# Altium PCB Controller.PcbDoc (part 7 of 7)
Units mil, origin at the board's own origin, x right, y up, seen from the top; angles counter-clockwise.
Board outline 9000 x 8000 mil, 6 copper layers (Top Layer, Layer 1, Layer 2, Layer 3, Layer 4, Bottom Layer), stack 61.699 mil thick; 761 components, 454 nets, 2369 pads, 1133 vias.
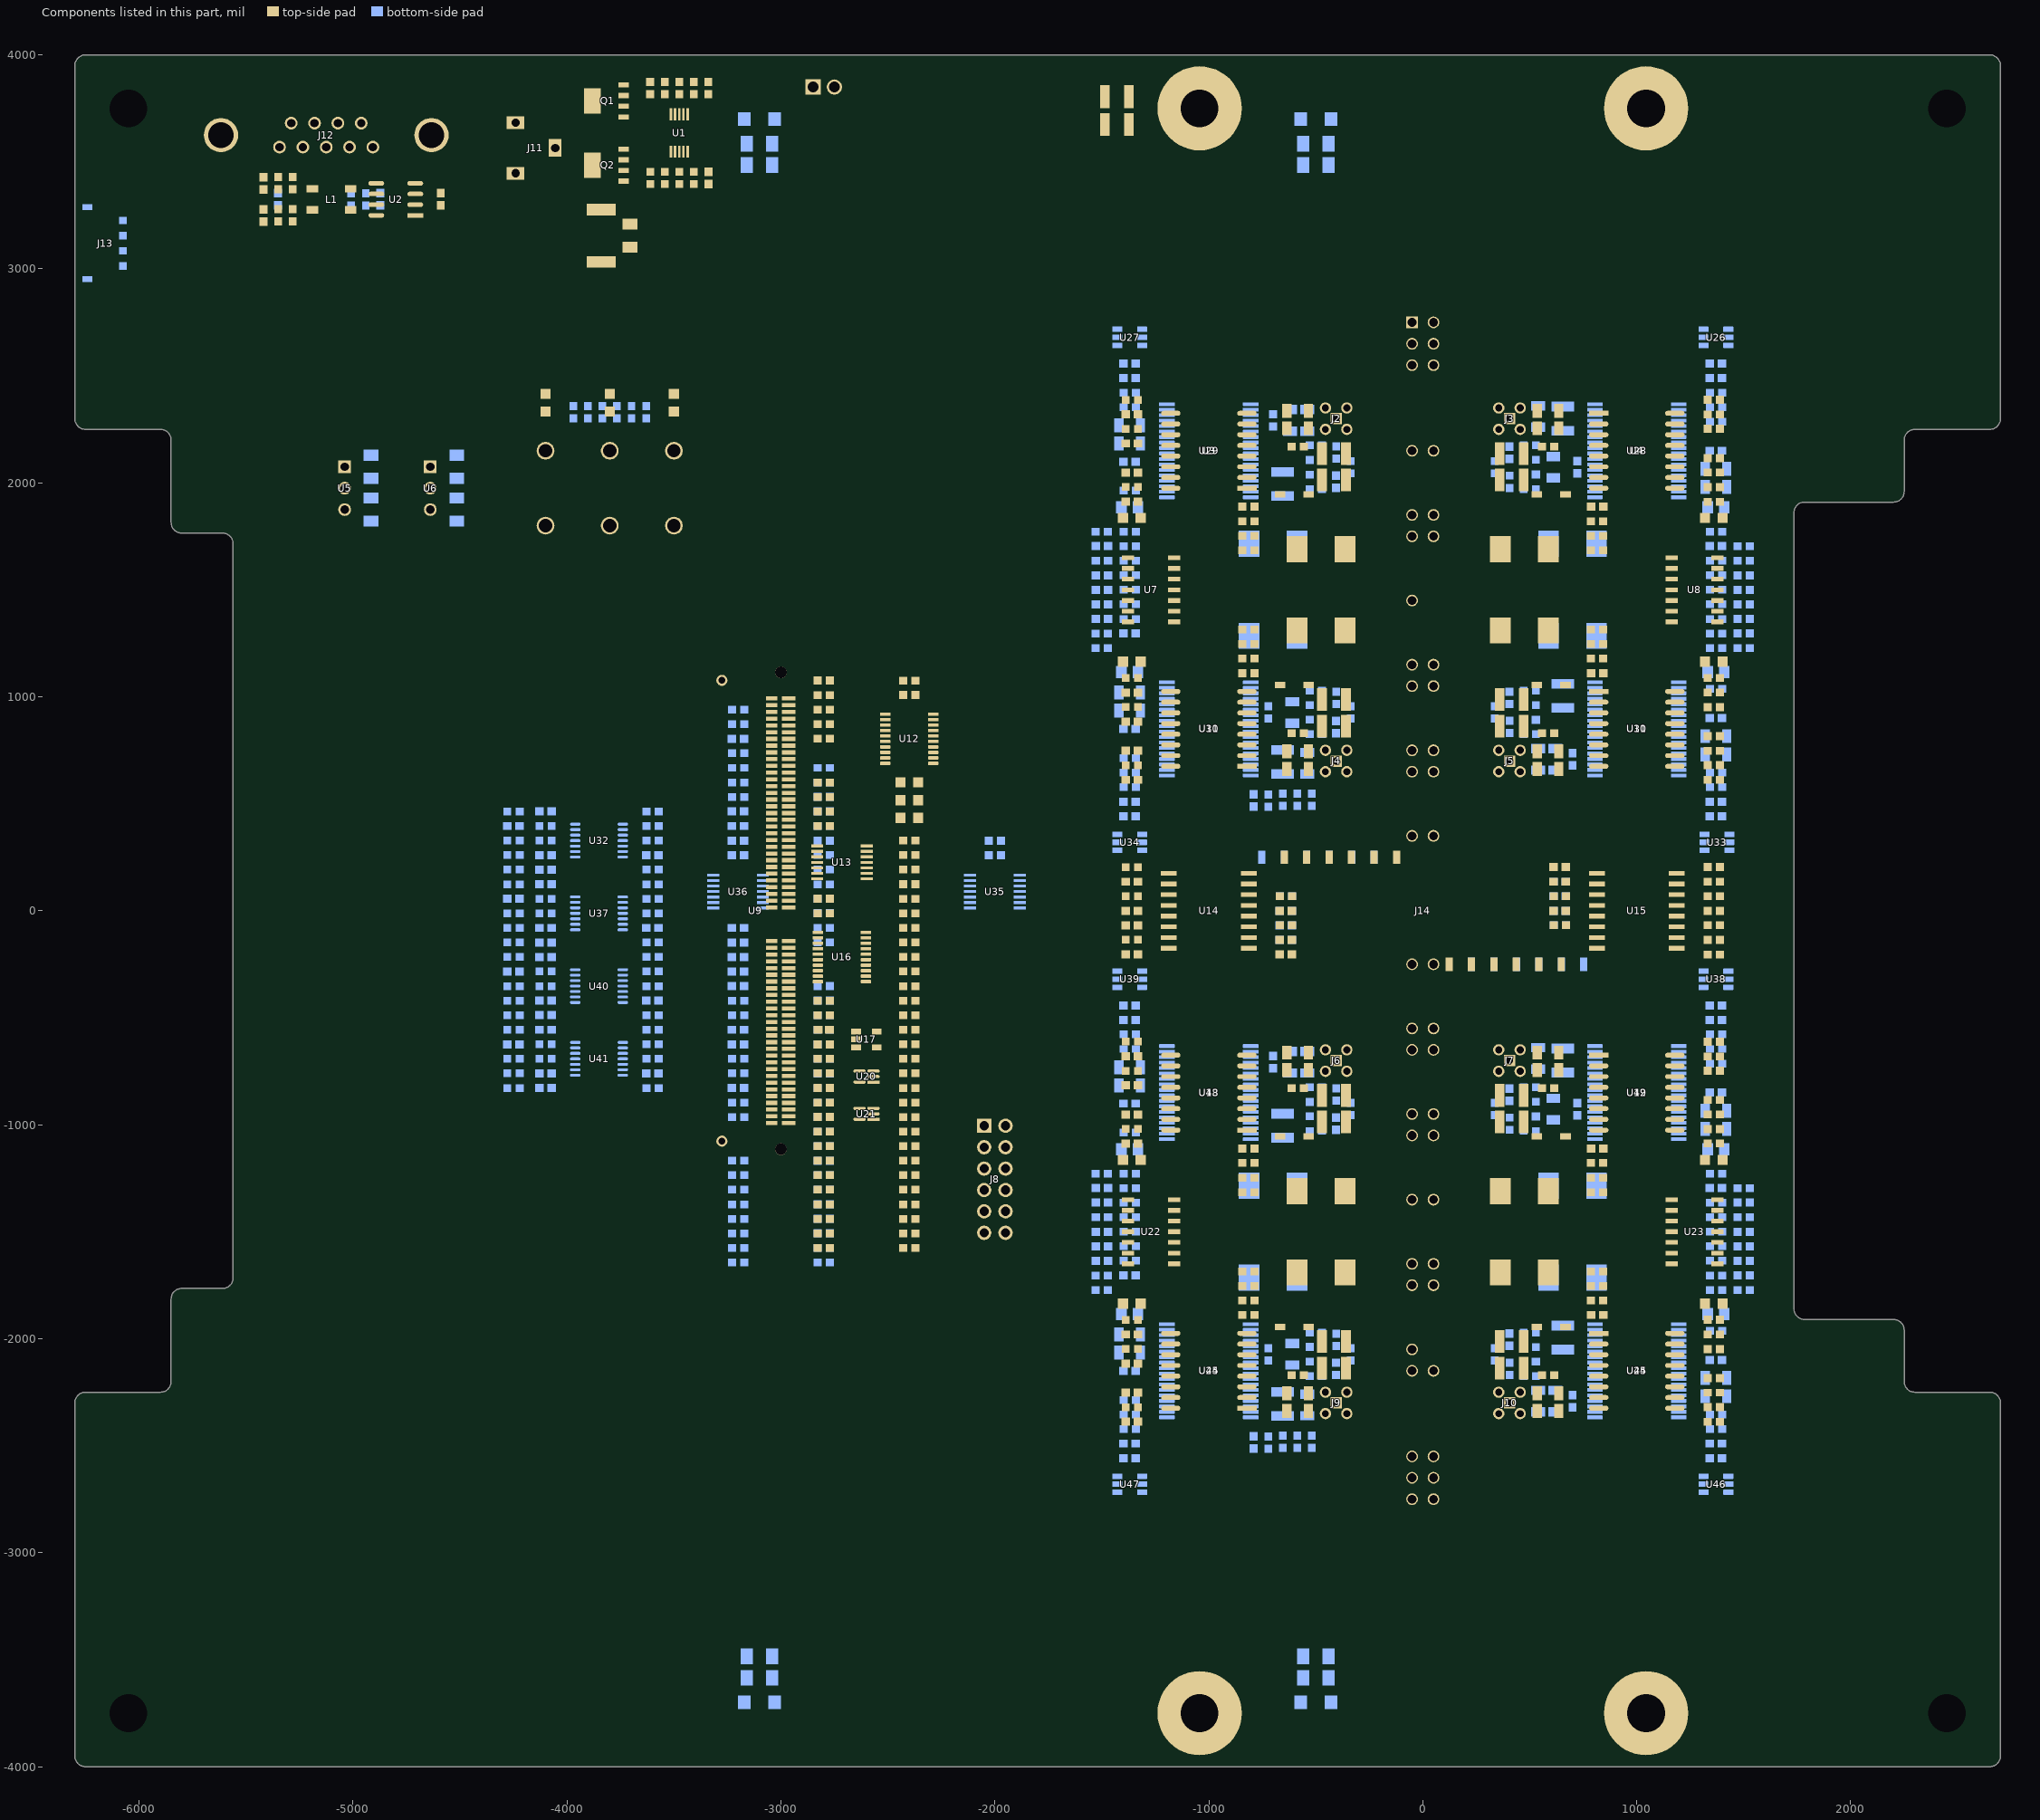
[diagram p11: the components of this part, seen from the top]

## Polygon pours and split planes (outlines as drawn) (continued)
CLMP_2P on Bottom Layer "CLMP_2P_L06_P195" (solid, pour order 195): -650,805 -650,840 -650,1030 -680,1030 -680,805
+15V_2P on Bottom Layer "+15V_2P_L06_P191" (solid, pour order 191): -845,800 -845,845 -760,845 -760,910 -705,910 -705,800
CLMP_4S on Bottom Layer "CLMP_4S_L06_P290" (solid, pour order 290): 650,-805 650,-840 650,-1030 680,-1030 680,-805
RLIM_4S on Bottom Layer "RLIM_4S_L06_P287" (solid, pour order 287): 840,-725 840,-745 765,-745 735,-775 590,-775 590,-735 600,-725
+15V_4S on Bottom Layer "+15V_4S_L06_P286" (solid, pour order 286): 845,-800 845,-845 760,-845 760,-910 705,-910 705,-800
-4V_3S on Bottom Layer "-4V_3S_L06_P262" (solid, pour order 262): -840,-1130 -840,-1160 -740,-1160 -740,-1090 -760,-1090 -760,-1030 -840,-1030
S_1S on Bottom Layer "S_1S_L06_P932" (solid, pour order 932): 755,-1915 560,-1915 560,-1980 755,-1980
-4V_1S on Bottom Layer "-4V_1S_L06_P302" (solid, pour order 302): 840,-2095 840,-2055 690,-2055 690,-2115 715,-2115 715,-2095
S_4P on Bottom Layer "NONET_L02_P-001" (solid, pour order 928): 600,2380 600,2330 740,2330 740,2380
-4V_4P on Bottom Layer "-4V_4P_L06_P032" (solid, pour order 32): 755,2415 755,2335 840,2335 840,2415
-4V_2P on Bottom Layer "-4V_2P_L06_P193" (solid, pour order 193): -715,620 -715,650 -735,670 -840,670 -840,620
GND on Bottom Layer "NONET_L-01_P-001" (solid, pour order 349): -1235,-1030 -1235,-1110 -1155,-1110 -1155,-1030
GND on Bottom Layer "NONET_L-01_P-001" (solid, pour order 357): 1235,-1970 1235,-1890 1155,-1890 1155,-1970
+12V on Bottom Layer "NONET_L-01_P-001" (solid, pour order 355): 1360,-2305 1360,-2075 1310,-2075 1310,-2045 1160,-2045 1160,-2095 1245,-2095 1245,-2140 1285,-2140 1285,-2305
GND on Bottom Layer "NONET_L-01_P-001" (solid, pour order 150): -1235,1970 -1235,1890 -1155,1890 -1155,1970
GND on Bottom Layer "NONET_L-01_P-001" (solid, pour order 238): 1235,1030 1235,1110 1155,1110 1155,1030
GND on Bottom Layer "NONET_L-01_P-001" (solid, pour order 356): 1270,-2425 1270,-2150 1235,-2150 1235,-2105 1160,-2105 1160,-2425
+15V_3P on Bottom Layer "+15V_3P_L06_P922" (solid, pour order 922): -840,2150 -840,2105 -555,2105 -555,2215 -505,2215 -505,2260 -760,2260 -760,2150
+15V_3S on Bottom Layer "+15V_3S_L06_P921" (solid, pour order 921): -840,-850 -840,-895 -555,-895 -555,-785 -505,-785 -505,-740 -760,-740 -760,-850
+15V_2P on Bottom Layer "+15V_2P_L06_P197" (solid, pour order 197): -570,955 -570,1030 -640,1030 -640,955
+15V_2S on Bottom Layer "+15V_2S_L06_P319" (solid, pour order 319): -570,-2045 -570,-1970 -640,-1970 -640,-2045
+15V_1S on Bottom Layer "+15V_1S_L06_P920" (solid, pour order 920): 840,-2150 840,-2105 555,-2105 555,-2215 505,-2215 505,-2260 760,-2260 760,-2150
+15V_4S on Bottom Layer "+15V_4S_L06_P292" (solid, pour order 292): 570,-955 570,-1030 640,-1030 640,-955
+15V_4P on Bottom Layer "+15V_4P_L06_P041" (solid, pour order 41): 570,2045 570,1970 640,1970 640,2045
GND on Bottom Layer "Bottom Layer-GND" (solid, pour order 916): 1505,-1710 ccw(c1530.12,-1709.88) 1530,-1735 1610,-1735 ccw(c1609.88,-1709.88) 1635,-1710 1635,-1355 ccw(c1609.88,-1355.12) 1610,-1330 1530,-1330 ccw(c1530.12,-1355.12) 1505,-1355
GND on Bottom Layer "Bottom Layer-GND 1" (solid, pour order 915): 1505,1290 ccw(c1530.12,1290.12) 1530,1265 1610,1265 ccw(c1609.88,1290.12) 1635,1290 1635,1645 ccw(c1609.88,1644.88) 1610,1670 1530,1670 ccw(c1530.12,1644.88) 1505,1645
CAN_MIDR on Bottom Layer "Bottom Layer-CAN_MIDR" (solid, pour order 909): 17 vertices, not listed, extent -5380,3160 -5265,3500
CAN_MIDC on Bottom Layer "Bottom Layer-CAN_MIDC" (solid, pour order 904): 17 vertices, not listed, extent -5455,3159.88 -5320,3500
GND on Bottom Layer "Bottom Layer-GND 2" (solid, pour order 883): -6014.88,3050 ccw(c-6015,3075) -5990,3074.88 -5990,3095.12 ccw(c-6015,3095) -6014.88,3120 -6135.12,3120 ccw(c-6135,3095) -6160,3095.12 -6160,3074.88 ccw(c-6135,3075) -6135.12,3050
+12V on Bottom Layer "Bottom Layer-+12V" (solid, pour order 878): -6014.88,2925 ccw(c-6015,2950) -5990,2949.88 -5990,3015.12 ccw(c-6015,3015) -6014.88,3040 -6135.12,3040 ccw(c-6135,3015) -6160,3015.12 -6160,2949.88 ccw(c-6135,2950) -6135.12,2925
+3.3V on Bottom Layer "Bottom Layer-+3.3V" (solid, pour order 873): 26 vertices, not listed, extent -5150,1785 -4870,3320
GND on Bottom Layer "Bottom Layer-GND 3" (solid, pour order 863): -4965,1915 ccw(c-4940.27,1920.29) -4940.14,1895 -4894.87,1895 ccw(c-4894.99,1919.99) -4870,1919.87 -4870,2030.12 ccw(c-4895,2030) -4894.87,2055 -4940.14,2055 ccw(c-4940.26,2029.69) -4965,2035 cw(c-4990,2035) -4989.88,2010 -5045.12,2010 ccw(c-5045,1985) -5070,1985.12 -5070,1964.88 ccw(c-5045,1965) -5045.12,1940 -4989.9,1940 cw(c-4990,1915)
GND on Bottom Layer "Bottom Layer-GND 4" (solid, pour order 862): -4565,1915 ccw(c-4540.27,1920.29) -4540.14,1895 -4494.87,1895 ccw(c-4494.99,1919.99) -4470,1919.87 -4470,2030.12 ccw(c-4495,2030) -4494.87,2055 -4540.14,2055 ccw(c-4540.26,2029.69) -4565,2035 cw(c-4590,2035) -4589.88,2010 -4645.12,2010 ccw(c-4645,1985) -4670,1985.12 -4670,1964.88 ccw(c-4645,1965) -4645.12,1940 -4589.9,1940 cw(c-4590,1915)
+12V on Bottom Layer "Bottom Layer-+12V 1" (solid, pour order 851): -4950.1,2070 -4894.88,2070 ccw(c-4892.54,2092.56) -4870,2090 -4870,2140.1 ccw(c-4895,2140) -4894.88,2165 -5045.12,2165 ccw(c-5045,2140) -5070,2140.12 -5070,2044.88 ccw(c-5045,2045) -5045.12,2020 -4999.88,2020 ccw(c-5000,2045) -4975,2045 -4975,2045.12 cw(c-4950,2045)
+5V on Bottom Layer "Bottom Layer-+5V" (solid, pour order 837): -4550.1,1880 -4494.88,1880 cw(c-4492.54,1857.44) -4470,1860 -4470,1809.9 cw(c-4495,1810) -4494.88,1785 -4645.12,1785 cw(c-4645,1810) -4670,1809.88 -4670,1905.12 cw(c-4645,1905) -4645.12,1930 -4599.88,1930 cw(c-4600,1905) -4575,1905 -4575,1904.88 ccw(c-4550,1905)
+12V on Bottom Layer "Bottom Layer-+12V 2" (solid, pour order 836): -4550.1,2070 -4494.88,2070 ccw(c-4492.54,2092.56) -4470,2090 -4470,2140.1 ccw(c-4495,2140) -4494.88,2165 -4645.12,2165 ccw(c-4645,2140) -4670,2140.12 -4670,2044.88 ccw(c-4645,2045) -4645.12,2020 -4599.88,2020 ccw(c-4600,2045) -4575,2045 -4575,2045.12 cw(c-4550,2045)
+5V on Bottom Layer "Bottom Layer-+5V 1" (solid, pour order 824): -4945,3205 -4935,3205 -4935,3245 -4905,3275 -4905,3320 -4945,3320 ccw(c-4944.03,3294.02) -4970,3295 -4970,3230 ccw(c-4944.94,3230.06)
GND on Bottom Layer "Bottom Layer-GND 5" (solid, pour order 818): -4849.88,3205 ccw(c-4850,3230) -4825,3229.88 -4825,3295.12 ccw(c-4850,3295) -4849.88,3320 -4895,3320 -4895,3270 -4925,3240 -4925,3205
NetC87_1 on Bottom Layer "Bottom Layer-NetC157_1" (solid, pour order 812): -5150,3354.88 ccw(c-5125,3355) -5125.12,3330 -4849.88,3330 ccw(c-4850,3355) -4825,3354.88 -4825,3405.12 ccw(c-4850,3405) -4849.88,3430 -5125.12,3430 ccw(c-5125,3405) -5150,3405.12
GND on Bottom Layer "NONET_L02_P-001" (solid, pour order 486): -1505,-1270 -1505,-1660 -1575,-1660 -1575,-1270
GND on Bottom Layer "NONET_L02_P-001" (solid, pour order 485): -1505,1730 -1505,1340 -1575,1340 -1575,1730
+12V on Bottom Layer "NONET_L-01_P-001" (solid, pour order 359): 1360,-1060 1360,-820 1310,-820 1310,-745 1160,-745 1160,-795 1245,-795 1245,-840 1285,-840 1285,-1060
S_4S on Bottom Layer "S_4S_L06_P294" (solid, pour order 294): 610,-620 610,-695 735,-695 735,-660 710,-660 710,-620
-4V_2S on Bottom Layer "-4V_2S_L06_P316" (solid, pour order 316): -845,-2150 -845,-1925 -840,-1920 -765,-1920 -765,-1955 -705,-1955 -705,-2060 -765,-2060 -765,-2150
-4V_2P on Bottom Layer "-4V_2P_L06_P194" (solid, pour order 194): -845,850 -845,1075 -840,1080 -765,1080 -765,1045 -705,1045 -705,940 -765,940 -765,850
-4V_4P on Bottom Layer "-4V_4P_L06_P036" (solid, pour order 36): 845,2150 845,1925 840,1920 765,1920 765,1955 705,1955 705,2060 765,2060 765,2150
GND on Bottom Layer "NONET_L-01_P-001" (solid, pour order 361): 1235,-670 1235,-590 1155,-590 1155,-670
GND on Bottom Layer "NONET_L-01_P-001" (solid, pour order 360): 1270,-1125 1270,-850 1235,-850 1235,-805 1160,-805 1160,-1125
GND on Bottom Layer "NONET_L-01_P-001" (solid, pour order 353): -1235,-2330 -1235,-2410 -1155,-2410 -1155,-2330
GND on Bottom Layer "NONET_L-01_P-001" (solid, pour order 352): -1270,-1875 -1270,-2150 -1235,-2150 -1235,-2195 -1160,-2195 -1160,-1875
+12V on Bottom Layer "NONET_L-01_P-001" (solid, pour order 351): -1360,-1945 -1360,-2180 -1310,-2180 -1310,-2255 -1160,-2255 -1160,-2205 -1245,-2205 -1245,-2160 -1285,-2160 -1285,-1945
GND on Bottom Layer "NONET_L-01_P-001" (solid, pour order 348): -1270,-575 -1270,-850 -1235,-850 -1235,-895 -1160,-895 -1160,-575
+12V on Bottom Layer "NONET_L-01_P-001" (solid, pour order 347): -1360,-695 -1360,-920 -1310,-920 -1310,-955 -1160,-955 -1160,-905 -1245,-905 -1245,-860 -1285,-860 -1285,-695
+15V_2S on Bottom Layer "Bottom Layer-+15V_2P" (solid, pour order 322): -615,-2475 -555,-2475 -555,-2395 -545,-2385 -505,-2385 -505,-2305 -595,-2305 -595,-2385 -615,-2405
S_2S on Bottom Layer "Bottom Layer-S_2P" (solid, pour order 321): -675,-2475 -635,-2475 -635,-2415 -605,-2385 -605,-2365 -605,-2305 -735,-2305 -735,-2340 -705,-2340 -705,-2385 -675,-2415
-4V_2S on Bottom Layer "-4V_2S_L06_P320" (solid, pour order 320): -510,-2280 -510,-2235 -535,-2210 -570,-2210 -570,-2280
-4V_2S on Bottom Layer "-4V_2S_L06_P318" (solid, pour order 318): -575,-2145 -575,-2055 -645,-2055 -645,-2145
CLMP_2S on Bottom Layer "CLMP_2S_L06_P317" (solid, pour order 317): -650,-2195 -650,-2160 -650,-1970 -680,-1970 -680,-2195
-4V_2S on Bottom Layer "-4V_2S_L06_P315" (solid, pour order 315): -715,-2380 -715,-2350 -735,-2330 -840,-2330 -840,-2380
RLIM_2S on Bottom Layer "RLIM_2S_L06_P314" (solid, pour order 314): -840,-2275 -840,-2255 -765,-2255 -735,-2225 -590,-2225 -590,-2265 -600,-2275
+15V_2S on Bottom Layer "+15V_2S_L06_P313" (solid, pour order 313): -845,-2200 -845,-2155 -760,-2155 -760,-2090 -705,-2090 -705,-2200
S_1S on Bottom Layer "S_1S_L06_P300" (solid, pour order 300): 575,-2380 575,-2305 440,-2305 440,-2380
-4V_1S on Bottom Layer "-4V_1S_L06_P299" (solid, pour order 299): 840,-2380 840,-2155 765,-2155 765,-2265 585,-2265 585,-2380
RLIM_1S on Bottom Layer "RLIM_1S_L06_P296" (solid, pour order 296): 840,-2045 840,-2000 575,-2000 575,-2080 685,-2080 685,-2045
-4V_4S on Bottom Layer "-4V_4S_L06_P295" (solid, pour order 295): 510,-720 510,-765 535,-790 570,-790 570,-720
+15V_4S on Bottom Layer "+15V_4S_L06_P293" (solid, pour order 293): 505,-620 505,-695 600,-695 600,-620
-4V_4S on Bottom Layer "-4V_4S_L06_P291" (solid, pour order 291): 575,-855 575,-945 645,-945 645,-855
-4V_4S on Bottom Layer "-4V_4S_L06_P289" (solid, pour order 289): 845,-850 845,-1075 840,-1080 765,-1080 765,-1045 705,-1045 705,-940 765,-940 765,-850
-4V_4S on Bottom Layer "-4V_4S_L06_P288" (solid, pour order 288): 715,-620 715,-650 735,-670 840,-670 840,-620
-4V_3S on Bottom Layer "-4V_3S_L06_P267" (solid, pour order 267): -840,-905 -840,-945 -690,-945 -690,-885 -715,-885 -715,-905
S_3S on Bottom Layer "S_3S_L06_P265" (solid, pour order 265): -575,-620 -575,-695 -440,-695 -440,-620
-4V_3S on Bottom Layer "-4V_3S_L06_P264" (solid, pour order 264): -840,-620 -840,-845 -765,-845 -765,-735 -585,-735 -585,-620
S_3S on Bottom Layer "S_3S_L06_P263" (solid, pour order 263): -755,-1085 -560,-1085 -560,-1020 -755,-1020
RLIM_3S on Bottom Layer "RLIM_3S_L06_P261" (solid, pour order 261): -840,-955 -840,-1000 -575,-1000 -575,-920 -685,-920 -685,-955
HLDOO_P on Bottom Layer "NONET_L02_P-001" (solid, pour order 250): -760,30 -760,-90 -645,-90 -645,30
GND on Bottom Layer "NONET_L-01_P-001" (solid, pour order 149): -1270,2425 -1270,2150 -1235,2150 -1235,2105 -1160,2105 -1160,2425
GND on Bottom Layer "NONET_L-01_P-001" (solid, pour order 241): -1270,1125 -1270,850 -1235,850 -1235,805 -1160,805 -1160,1125
GND on Bottom Layer "NONET_L-01_P-001" (solid, pour order 242): -1235,670 -1235,590 -1155,590 -1155,670
GND on Bottom Layer "NONET_L-01_P-001" (solid, pour order 245): 1270,1875 1270,2150 1235,2150 1235,2195 1160,2195 1160,1875
GND on Bottom Layer "NONET_L-01_P-001" (solid, pour order 246): 1235,2330 1235,2410 1155,2410 1155,2330
+12V on Bottom Layer "NONET_L-01_P-001" (solid, pour order 244): 1360,1945 1360,2180 1310,2180 1310,2255 1160,2255 1160,2205 1245,2205 1245,2160 1285,2160 1285,1945
+12V on Bottom Layer "NONET_L-01_P-001" (solid, pour order 240): -1360,1054.3 -1360,820 -1310,820 -1310,745 -1160,745 -1160,795 -1245,795 -1245,840 -1285,840 -1285,1054.3
+12V on Bottom Layer "NONET_L-01_P-001" (solid, pour order 236): 1360,695 1360,920 1310,920 1310,955 1160,955 1160,905 1245,905 1245,860 1285,860 1285,695
+12V on Bottom Layer "NONET_L-01_P-001" (solid, pour order 148): -1360,2305 -1360,2080 -1310,2080 -1310,2045 -1160,2045 -1160,2095 -1245,2095 -1245,2140 -1285,2140 -1285,2305
+15V_2P on Bottom Layer "Bottom Layer-+15V_2P" (solid, pour order 206): -615,525 -555,525 -555,605 -545,615 -505,615 -505,695 -595,695 -595,615 -615,595
-4V_2P on Bottom Layer "-4V_2P_L06_P200" (solid, pour order 200): -510,720 -510,765 -535,790 -570,790 -570,720
-4V_2P on Bottom Layer "-4V_2P_L06_P196" (solid, pour order 196): -575,855 -575,945 -645,945 -645,855
-4V_1P on Bottom Layer "-4V_1P_L06_P112" (solid, pour order 112): 840,905 840,945 690,945 690,885 715,885 715,905
+15V_1P on Bottom Layer "+15V_1P_L06_P111" (solid, pour order 111): 840,850 840,895 555,895 555,785 505,785 505,740 760,740 760,850
S_1P on Bottom Layer "S_1P_L06_P110" (solid, pour order 110): 575,620 575,695 440,695 440,620
-4V_1P on Bottom Layer "-4V_1P_L06_P109" (solid, pour order 109): 840,620 840,845 765,845 765,735 585,735 585,620
S_1P on Bottom Layer "S_1P_L06_P108" (solid, pour order 108): 755,1085 560,1085 560,1020 755,1020
RLIM_1P on Bottom Layer "RLIM_1P_L06_P106" (solid, pour order 106): 840,955 840,1000 575,1000 575,920 685,920 685,955
-4V_3P on Bottom Layer "-4V_3P_L06_P016" (solid, pour order 16): -840,2380 -840,2155 -765,2155 -765,2265 -585,2265 -585,2380
-4V_4P on Bottom Layer "-4V_4P_L06_P046" (solid, pour order 46): 510,2280 510,2235 535,2210 570,2210 570,2280
S_4P on Bottom Layer "S_4P_L06_P044" (solid, pour order 44): 610,2380 610,2305 735,2305 735,2340 710,2340 710,2380
+15V_4P on Bottom Layer "+15V_4P_L06_P043" (solid, pour order 43): 505,2380 505,2305 600,2305 600,2380
-4V_4P on Bottom Layer "-4V_4P_L06_P040" (solid, pour order 40): 575,2145 575,2055 645,2055 645,2145
S_3P on Bottom Layer "S_3P_L06_P004" (solid, pour order 4): -755,1915 -560,1915 -560,1980 -755,1980
RLIM_3P on Bottom Layer "RLIM_3P_L06_P001" (solid, pour order 1): -840,2045 -840,2000 -575,2000 -575,2080 -685,2080 -685,2045
-4V_3P on Bottom Layer "-4V_3P_L06_P023" (solid, pour order 23): -840,2095 -840,2055 -690,2055 -690,2115 -715,2115 -715,2095
S_3P on Bottom Layer "S_3P_L06_P017" (solid, pour order 17): -575,2380 -575,2305 -440,2305 -440,2380
+5V on Layer 3 "Layer 3-+5V 1" (solid, pour order 711): 27 vertices, not listed, extent -100,-3900 1635,3900
+5V on Layer 3 "Layer 3-+5V" (solid, pour order 705): 59 vertices, not listed, extent -6200,-3900 115,3900
-4V_3P on Layer 3 "Layer 1-S_4P" (solid, pour order 114): -350,1910 ccw(c-350,1935) -325,1935 -325,2355.33 ccw(c-350,2355) -349.88,2380 -845.12,2380 ccw(c-845,2355) -870,2355.12 -870,1644.88 ccw(c-845,1645) -845.12,1620 -784.88,1620 ccw(c-785,1645) -760,1644.88 -760,1830 -680.02,1909.98
-4V_1S on Layer 3 "Layer 3--4V_1P" (solid, pour order 334): 349.88,-2380 845.12,-2380 ccw(c845,-2355) 870,-2355.12 870,-1644.88 ccw(c845.01,-1645) 845.12,-1620 784.88,-1620 ccw(c784.99,-1644.99) 760,-1644.88 760,-1830 680.02,-1909.98 349.92,-1910 ccw(c350,-1935) 325,-1935 325,-2355 ccw(c350,-2355)
-4V_4P on Layer 3 "Layer 3--4V_3P" (solid, pour order 179): 784.88,1615 840.12,1615 ccw(c840,1640) 865,1639.88 865,2385.12 ccw(c840,2385) 840.12,2410 334.88,2410 ccw(c334.93,2385.06) 310,2385.12 310,1955 ccw(c335,1955) 334.88,1930 685,1930 760,1855 760,1639.88 ccw(c785,1640)
-4V_1P on Layer 3 "Layer 3--4V_1P" (solid, pour order 145): 349.88,620 845.12,620 ccw(c845,645) 870,644.88 870,1355.12 ccw(c845.01,1355) 845.12,1380 784.88,1380 ccw(c784.99,1355.01) 760,1355.12 760,1170 680.02,1090.02 349.92,1090 ccw(c350,1065) 325,1065 325,645 ccw(c350,645)
-4V_2P on Layer 3 "Layer 3--4V_2P" (solid, pour order 229): 17 vertices, not listed, extent -865,455 -290,1385
-4V_4S on Layer 3 "Layer 3--4V_3P" (solid, pour order 335): 784.88,-1385 840.12,-1385 ccw(c840,-1360) 865,-1360.12 865,-629.88 ccw(c840,-630) 840.12,-605 334.88,-605 ccw(c334.93,-629.93) 310,-629.88 310,-1045 ccw(c335,-1045) 334.88,-1070 685,-1070 760,-1145 760,-1360.12 ccw(c785,-1360)
-4V_3S on Layer 3 "Layer 1-S_4P" (solid, pour order 328): -350,-1090 ccw(c-350,-1065) -325,-1065 -325,-644.67 ccw(c-350,-645) -349.88,-620 -845.12,-620 ccw(c-845,-645) -870,-644.88 -870,-1355.12 ccw(c-845,-1355) -845.12,-1380 -784.88,-1380 ccw(c-785,-1355) -760,-1355.12 -760,-1170 -680.02,-1090.02
-4V_2S on Layer 3 "Layer 3--4V_2P" (solid, pour order 336): 17 vertices, not listed, extent -865,-2545 -290,-1615
VIN on Layer 3 "Layer 3-VIN" (solid, pour order 517): -3349.88,2940 ccw(c-3350,2965) -3325,2964.88 -3325,3875.12 ccw(c-3350,3875) -3349.88,3900 -4295.12,3900 ccw(c-4295,3875) -4320,3875.12 -4320,2964.88 ccw(c-4295,2965) -4295.12,2940
GND on Layer 1 "Layer 1-GND 1" (solid, pour order 664): 27 vertices, not listed, extent -100,-3900 1635,3900
GND on Layer 1 "Layer 1-GND" (solid, pour order 670): 51 vertices, not listed, extent -6200,-3900 115,3900
S_3P on Layer 1 "Layer 1-S_3P" (solid, pour order 411): 17 vertices, not listed, extent -870,1620 80,2380
S_4P on Layer 1 "Layer 1-S_4P 1" (solid, pour order 409): 18 vertices, not listed, extent -75,1615 865,2410
S_1P on Layer 1 "Layer 1-S_1P" (solid, pour order 137): 23 vertices, not listed, extent -85,620 870,1380
S_2P on Layer 1 "Layer 1-S_2P" (solid, pour order 222): 21 vertices, not listed, extent -865,455 95,1385
S_4S on Layer 1 "Layer 1-S_4S" (solid, pour order 431): 19 vertices, not listed, extent -90,-1385 865,-505
S_2S on Layer 1 "Layer 1-S_2S" (solid, pour order 449): 29 vertices, not listed, extent -865,-2545 80,-1615
S_1S on Layer 1 "Layer 1-S_1S" (solid, pour order 453): 20 vertices, not listed, extent -85,-2380 870,-1595
S_3S on Layer 1 "Layer 1-S_3S" (solid, pour order 401): 18 vertices, not listed, extent -870,-1380 75,-620
GND_P on Layer 1 "Layer 1-GND_P" (solid, pour order 422): -559.88,-235 ccw(c-560,-210) -535,-210.12 -535,85.12 ccw(c-560,85) -559.88,110 -710.12,110 cw(c-710,135) -735,134.88 -735,420.12 ccw(c-760,420) -759.88,445 -840.12,445 ccw(c-840,420) -865,420.12 -865,-210.12 ccw(c-840,-210) -840.12,-235
GND_S on Layer 1 "Layer 1-GND_S" (solid, pour order 434): 559.88,-110 710.12,-110 cw(c710,-135) 735,-134.88 735,-570.12 ccw(c760,-570) 759.88,-595 840.12,-595 ccw(c840,-570) 865,-570.12 865,210.12 ccw(c840,210) 840.12,235 559.88,235 ccw(c560,210) 535,210.12 535,-85.12 ccw(c560,-85)
+12V on Layer 2 "Layer 2-+12V 1" (solid, pour order 796): 27 vertices, not listed, extent -100,-3900 1635,3900
+12V on Layer 2 "Layer 2-+12V" (solid, pour order 799): 59 vertices, not listed, extent -6200,-3900 115,3900
+3.3V on Layer 2 "Layer 2-+3.3V" (solid, pour order 734): -2054.88,-1990 ccw(c-2055,-1965) -2030,-1965.12 -2030,2225.12 ccw(c-2055,2225) -2054.88,2250 -3565.12,2250 ccw(c-3565,2225) -3590,2225.12 -3590,1949.88 cw(c-3615,1950) -3614.88,1925 -5435.12,1925 ccw(c-5435,1900) -5460,1900.12 -5460,-1965.12 ccw(c-5432.44,-1962.41) -5430,-1990
+15V_3P on Layer 2 "Layer 1-S_4P" (solid, pour order 113): -350,1910 ccw(c-350,1935) -325,1935 -325,2355.33 ccw(c-350,2355) -349.88,2380 -845.12,2380 ccw(c-845,2355) -870,2355.12 -870,1644.88 ccw(c-845,1645) -845.12,1620 -784.88,1620 ccw(c-785,1645) -760,1644.88 -760,1830 -680.02,1909.98
+15V_1S on Layer 2 "Layer 2-+15V_1P" (solid, pour order 371): 349.88,-2380 845.12,-2380 ccw(c845,-2355) 870,-2355.12 870,-1644.88 ccw(c845.01,-1645) 845.12,-1620 784.88,-1620 ccw(c784.99,-1644.99) 760,-1644.88 760,-1830 680.02,-1909.98 349.92,-1910 ccw(c350,-1935) 325,-1935 325,-2355 ccw(c350,-2355)
+15V_4P on Layer 2 "Layer 2-+15V_3P" (solid, pour order 178): 784.88,1615 840.12,1615 ccw(c840,1640) 865,1639.88 865,2385.12 ccw(c840,2385) 840.12,2410 334.88,2410 ccw(c334.93,2385.06) 310,2385.12 310,1955 ccw(c335,1955) 334.88,1930 685,1930 760,1855 760,1639.88 ccw(c785,1640)
+15V_1P on Layer 2 "Layer 2-+15V_1P" (solid, pour order 144): 349.88,620 845.12,620 ccw(c845,645) 870,644.88 870,1355.12 ccw(c845.01,1355) 845.12,1380 784.88,1380 ccw(c784.99,1355.01) 760,1355.12 760,1170 680.02,1090.02 349.92,1090 ccw(c350,1065) 325,1065 325,645 ccw(c350,645)
+15V_2P on Layer 2 "Layer 2-+15V_2P" (solid, pour order 228): 17 vertices, not listed, extent -865,455 -290,1385
+15V_4S on Layer 2 "Layer 2-+15V_3P" (solid, pour order 374): 784.88,-1385 840.12,-1385 ccw(c840,-1360) 865,-1360.12 865,-629.88 ccw(c840,-630) 840.12,-605 334.88,-605 ccw(c334.93,-629.93) 310,-629.88 310,-1045 ccw(c335,-1045) 334.88,-1070 685,-1070 760,-1145 760,-1360.12 ccw(c785,-1360)
+15V_3S on Layer 2 "Layer 1-S_4P" (solid, pour order 327): -350,-1090 ccw(c-350,-1065) -325,-1065 -325,-644.67 ccw(c-350,-645) -349.88,-620 -845.12,-620 ccw(c-845,-645) -870,-644.88 -870,-1355.12 ccw(c-845,-1355) -845.12,-1380 -784.88,-1380 ccw(c-785,-1355) -760,-1355.12 -760,-1170 -680.02,-1090.02
+15V_2S on Layer 2 "Layer 2-+15V_2P" (solid, pour order 333): 17 vertices, not listed, extent -865,-2545 -290,-1615
GND on Layer 4 "Layer 1-GND 1" (solid, pour order 923): 27 vertices, not listed, extent -100,-3900 1635,3900
GND on Layer 4 "Layer 1-GND" (solid, pour order 924): 51 vertices, not listed, extent -6200,-3900 115,3900
S_3P on Layer 4 "Layer 1-S_4P" (solid, pour order 115): -350,1910 ccw(c-350,1935) -325,1935 -325,2355.33 ccw(c-350,2355) -349.88,2380 -845.12,2380 ccw(c-845,2355) -870,2355.12 -870,1644.88 ccw(c-845,1645) -845.12,1620 -784.88,1620 ccw(c-785,1645) -760,1644.88 -760,1830 -680.02,1909.98
S_4P on Layer 4 "Layer 4-S_3P" (solid, pour order 180): 784.88,1615 840.12,1615 ccw(c840,1640) 865,1639.88 865,2385.12 ccw(c840,2385) 840.12,2410 334.88,2410 ccw(c334.93,2385.06) 310,2385.12 310,1955 ccw(c335,1955) 334.88,1930 685,1930 760,1855 760,1639.88 ccw(c785,1640)
S_1P on Layer 4 "Layer 4-S_1P" (solid, pour order 146): 349.88,620 845.12,620 ccw(c845,645) 870,644.88 870,1355.12 ccw(c845.01,1355) 845.12,1380 784.88,1380 ccw(c784.99,1355.01) 760,1355.12 760,1170 680.02,1090.02 349.92,1090 ccw(c350,1065) 325,1065 325,645 ccw(c350,645)
S_2P on Layer 4 "Layer 4-S_2P" (solid, pour order 230): 17 vertices, not listed, extent -865,455 -290,1385
S_4S on Layer 4 "Layer 4-S_3P" (solid, pour order 338): 784.88,-1385 840.12,-1385 ccw(c840,-1360) 865,-1360.12 865,-629.88 ccw(c840,-630) 840.12,-605 334.88,-605 ccw(c334.93,-629.93) 310,-629.88 310,-1045 ccw(c335,-1045) 334.88,-1070 685,-1070 760,-1145 760,-1360.12 ccw(c785,-1360)
GND_P on Layer 4 "Layer 1-GND_P" (solid, pour order 800): -559.88,-235 ccw(c-560,-210) -535,-210.12 -535,85.12 ccw(c-560,85) -559.88,110 -710.12,110 cw(c-710,135) -735,134.88 -735,420.12 ccw(c-760,420) -759.88,445 -840.12,445 ccw(c-840,420) -865,420.12 -865,-210.12 ccw(c-840,-210) -840.12,-235
GND_S on Layer 4 "Layer 1-GND_S" (solid, pour order 801): 559.88,-110 710.12,-110 cw(c710,-135) 735,-134.88 735,-570.12 ccw(c760,-570) 759.88,-595 840.12,-595 ccw(c840,-570) 865,-570.12 865,210.12 ccw(c840,210) 840.12,235 559.88,235 ccw(c560,210) 535,210.12 535,-85.12 ccw(c560,-85)
S_2S on Layer 4 "Layer 4-S_2P" (solid, pour order 339): 17 vertices, not listed, extent -865,-2545 -290,-1615
S_1S on Layer 4 "Layer 4-S_1P" (solid, pour order 337): 349.88,-2380 845.12,-2380 ccw(c845,-2355) 870,-2355.12 870,-1644.88 ccw(c845.01,-1645) 845.12,-1620 784.88,-1620 ccw(c784.99,-1644.99) 760,-1644.88 760,-1830 680.02,-1909.98 349.92,-1910 ccw(c350,-1935) 325,-1935 325,-2355 ccw(c350,-2355)
S_3S on Layer 4 "Layer 1-S_4P" (solid, pour order 329): -350,-1090 ccw(c-350,-1065) -325,-1065 -325,-644.67 ccw(c-350,-645) -349.88,-620 -845.12,-620 ccw(c-845,-645) -870,-644.88 -870,-1355.12 ccw(c-845,-1355) -845.12,-1380 -784.88,-1380 ccw(c-785,-1355) -760,-1355.12 -760,-1170 -680.02,-1090.02

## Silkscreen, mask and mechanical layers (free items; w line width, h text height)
Top Overlay:
  drawing of 281 lines, arcs and shapes, not listed
  text "+" at -4440,3780 h60
  text "+" at -2861.66,3672.51 h35
  text "-" at -2761.66,3672.51 h35
  text "-" at -4440,3510.01 h60
  text "(G3P)" at -477.89,2391 h35
  text "(G4P)" at 332.11,2391 h35
  text "(ROFF)" at -319,2091.51 h35
  text "(RON)" at 173.21,2091.51 h35
  text "(+12V)" at -4187.47,2032.51 h35
  text "(+5V)" at -3872.89,2032.51 h35
  text "(+3.3V)" at -3604.97,2032.51 h35
  text "(RON)" at -319,1967.51 h35
  text "(ROFF)" at 138.23,1967.51 h35
  text "(FLT3P)" at -1284,1818.51 h35
  text "(FLT4P)" at 1068.24,1818.51 h35
  text "(GND)" at -4172.89,1682.51 h35
  text "(GND)" at -3872.89,1682.51 h35
  text "(GND)" at -3572.89,1682.51 h35
  text "(FLT2P)" at -1284,1146.51 h35
  text "(FLT1P)" at 1074.07,1146.51 h35
  text "(ROFF)" at -319,941.51 h35
  text "(RON)" at 173.21,941.51 h35
  text "(RON)" at -319,817.51 h35
  text "(ROFF)" at 138.23,817.51 h35
  text "(G2P)" at -477.89,574.01 h35
  text "(G1P)" at 335.02,574.01 h35
  text "3.3" at -2118.74,-367.49 h35
  text "5V" at -1954.16,-367.49 h35
  text "(POWER)" at -1829,-367.49 h35
  text "B4" at -2104.16,-467.49 h35
  text "B3" at -1954.16,-467.49 h35
  text "(ADC)" at -1829,-467.49 h35
  text "8A" at -2104.16,-567.49 h35
  text "8B" at -1954.16,-567.49 h35
  text "(EPWM)" at -1829,-567.49 h35
  text "(G3S)" at -477.89,-609 h35
  text "(G4S)" at 332.11,-609 h35
  text "8" at -2086.66,-667.49 h35
  text "9" at -1936.66,-667.49 h35
  text "(GPIO)" at -1829,-717.49 h35
  text "22" at -2104.16,-767.49 h35
  text "23" at -1954.16,-767.49 h35
  text "GND" at -2121.65,-867.49 h35
  text "12V" at -1968.74,-867.49 h35
  text "(POWER)" at -1829,-867.49 h35
  text "(ROFF)" at -319,-908.49 h35
  text "(RON)" at 173.21,-908.49 h35
  text "(RON)" at -319,-1032.49 h35
  text "(ROFF)" at 138.23,-1032.49 h35
  text "(FLT3S)" at -1284,-1181.49 h35
  text "(FLT4S)" at 1068.24,-1181.49 h35
  text "(FLT2S)" at -1284,-1853.49 h35
  text "(FLT1S)" at 1074.07,-1853.49 h35
  text "(ROFF)" at -319,-2058.49 h35
  text "(RON)" at 173.21,-2058.49 h35
  text "(RON)" at -319,-2182.49 h35
  text "(ROFF)" at 138.23,-2182.49 h35
  text "(G2S)" at -477.89,-2425.99 h35
  text "(G1S)" at 335.02,-2425.99 h35
  text "WOLFPACK 60KW DAB - CONTROL" at -799.74,-3790 h60
  text "CRD60DD12N-GMB V2.0, 02/2025" at -819.73,-3885.01 h60
Bottom Overlay:
  lines w8: -4739.7,-181.7 -4297.48,-181.7 ; -4737.7,157.7 -4297.48,157.7 ; -4737.3,-522.3 -4297.48,-522.3
  lines w10: -4740,-860 -4738.3,-861.7 ; -4740,-182 -4739.7,-181.7 ; -4740,160 -4737.7,157.7 ; -4737.7,497.7 -4740,500 ; -500,-2395 -495,-2400 -460,-2400 ; -500,605 -495,600 -460,600 ; -485,-1935 -485,-1920 ; -485,-1065 -485,-1080 ; -485,1065 -485,1080 ; -485,1935 -485,1920 ; -300,-2073 -285,-2073 ; -300,-927 -285,-927 ; -300,927 -285,927 ; -300,2073 -285,2073 ; 285,-2073 300,-2073 ; 285,-926.09 300,-926.09 ; 285,927 300,927 ; 285,2073 300,2073 ; 485,-1935 485,-1920 ; 485,1065 485,1080 ; 485,1935 485,1920 ; 485.91,-1080 485.91,-1065 ; -4740,500 -4360,500 -4360,-865 -4740,-865 -4740,500 ; -485,-1920 -315,-1920 -315,-1675 -485,-1675 -485,-1920 ; -485,-1080 -315,-1080 -315,-1325 -485,-1325 -485,-1080 ; -485,1080 -315,1080 -315,1325 -485,1325 -485,1080 ; -485,1920 -315,1920 -315,1675 -485,1675 -485,1920 ; 485,-1920 315,-1920 315,-1675 485,-1675 485,-1920 ; 485,1080 315,1080 315,1325 485,1325 485,1080 ; 485,1920 315,1920 315,1675 485,1675 485,1920 ; -460,-2565 -325,-2565 -325,-2399 -460,-2399 -460,-2565 ; -460,435 -325,435 -325,601 -460,601 -460,435 ; -285,-2238 -150,-2238 -150,-1908 -285,-1908 -285,-2238 ; -285,-1092 -150,-1092 -150,-762 -285,-762 -285,-1092 ; -285,762 -150,762 -150,1092 -285,1092 -285,762 ; -285,1908 -150,1908 -150,2238 -285,2238 -285,1908 ; 150,-2238 285,-2238 285,-1908 150,-1908 150,-2238 ; 150,-1091.09 285,-1091.09 285,-761.09 150,-761.09 150,-1091.09 ; 150,762 285,762 285,1092 150,1092 150,762 ; 150,1908 285,1908 285,2238 150,2238 150,1908 ; 315,-1325 485,-1325 485,-1080 315,-1080 315,-1325
  text "L" at -6007.51,3236.66 h35 r90
  text "H" at -6007.51,3167.1 h35 r90
  text "-" at -6007.51,3096.23 h35 r90
  text "+" at -6007.51,3025.36 h35 r90
Board Shape:
  the board outline again, w10
Drill Drawing:
  drawing of 201 lines, arcs and shapes, not listed
  text "Symbol" at -6202.5,6628.94 h72
  text "Count" at -5696.62,6628.94 h72
  text "Hole Size" at -5046.8,6628.94 h72
  text "Plated" at -3957.12,6628.94 h72
  text "Hole Type" at -3451.24,6628.94 h72
  text "Drill Layer Pair" at -2717.44,6628.94 h72
  text "Via/Pad" at -1217.89,6628.94 h72
  text "Pad Shape" at -628.04,6628.94 h72
  text "Hole Tolerance (+)" at 117.76,6628.94 h72
  text "Hole Tolerance (-)" at 1451.37,6628.94 h72
  text "Hole Length" at 2784.97,6628.94 h72
  text "Routed Path Length" at 3814.68,6628.94 h72
  text "1133" at -5696.62,6478.94 h60
  text "0.33mm (13.00mil)" at -5046.8,6478.94 h60
  text "PTH" at -3957.12,6478.94 h60
  text "Round" at -3451.24,6478.94 h60
  text "Top Layer - Bottom Layer" at -2717.44,6478.94 h60
  text "Via" at -1217.89,6478.94 h60
  text "Rounded" at -628.04,6478.94 h60
  text "0.08mm (3.00mil)" at 117.76,6478.94 h60
  text "0.08mm (3.00mil)" at 1451.37,6478.94 h60
  text "-" at 2784.97,6478.94 h60
  text "-" at 3814.68,6478.94 h60
  text "2" at -5696.62,6328.94 h60
  text "0.81mm (31.89mil)" at -5046.8,6328.94 h60
  text "PTH" at -3957.12,6328.94 h60
  text "Round" at -3451.24,6328.94 h60
  text "Top Layer - Bottom Layer" at -2717.44,6328.94 h60
  text "Pad" at -1217.89,6328.94 h60
  text "Rounded" at -628.04,6328.94 h60
  text "0.08mm (3.00mil)" at 117.76,6328.94 h60
  text "0.08mm (3.00mil)" at 1451.37,6328.94 h60
  text "-" at 2784.97,6328.94 h60
  text "-" at 3814.68,6328.94 h60
  text "40" at -5696.62,6178.94 h60
  text "0.84mm (33.07mil)" at -5046.8,6178.94 h60
  text "PTH" at -3957.12,6178.94 h60
  text "Round" at -3451.24,6178.94 h60
  text "Top Layer - Bottom Layer" at -2717.44,6178.94 h60
  text "Pad" at -1217.89,6178.94 h60
  text "(Mixed)" at -628.04,6178.94 h60
  text "0.08mm (3.00mil)" at 117.76,6178.94 h60
  text "0.08mm (3.00mil)" at 1451.37,6178.94 h60
  text "-" at 2784.97,6178.94 h60
  text "-" at 3814.68,6178.94 h60
  text "15" at -5696.62,6028.94 h60
  text "1.00mm (39.37mil)" at -5046.8,6028.94 h60
  text "PTH" at -3957.12,6028.94 h60
  text "Round" at -3451.24,6028.94 h60
  text "Top Layer - Bottom Layer" at -2717.44,6028.94 h60
  text "Pad" at -1217.89,6028.94 h60
  text "(Mixed)" at -628.04,6028.94 h60
  text "0.08mm (3.00mil)" at 117.76,6028.94 h60
  text "0.08mm (3.00mil)" at 1451.37,6028.94 h60
  text "-" at 2784.97,6028.94 h60
  text "-" at 3814.68,6028.94 h60
  text "3" at -5696.62,5878.94 h60
  text "1.00mm (39.37mil)" at -5046.8,5878.94 h60
  text "PTH" at -3957.12,5878.94 h60
  text "Slot" at -3451.24,5878.94 h60
  text "Top Layer - Bottom Layer" at -2717.44,5878.94 h60
  text "Pad" at -1217.89,5878.94 h60
  text "Rectangle" at -628.04,5878.94 h60
  text "0.08mm (3.00mil)" at 117.76,5878.94 h60
  text "0.08mm (3.00mil)" at 1451.37,5878.94 h60
  text "1.60mm (62.99mil)" at 2784.97,5878.94 h60
  text "0.60mm (23.62mil)" at 3814.68,5878.94 h60
  text "48" at -5696.62,5728.94 h60
  text "1.04mm (40.95mil)" at -5046.8,5728.94 h60
  text "PTH" at -3957.12,5728.94 h60
  text "Round" at -3451.24,5728.94 h60
  text "Top Layer - Bottom Layer" at -2717.44,5728.94 h60
  text "Pad" at -1217.89,5728.94 h60
  text "Rounded" at -628.04,5728.94 h60
  text "0.08mm (3.00mil)" at 117.76,5728.94 h60
  text "0.08mm (3.00mil)" at 1451.37,5728.94 h60
  text "-" at 2784.97,5728.94 h60
  text "-" at 3814.68,5728.94 h60
  text "12" at -5696.62,5578.94 h60
  text "1.10mm (43.31mil)" at -5046.8,5578.94 h60
  text "PTH" at -3957.12,5578.94 h60
  text "Round" at -3451.24,5578.94 h60
  text "Top Layer - Bottom Layer" at -2717.44,5578.94 h60
  text "Pad" at -1217.89,5578.94 h60
  text "(Mixed)" at -628.04,5578.94 h60
  text "0.08mm (3.00mil)" at 117.76,5578.94 h60
  text "0.08mm (3.00mil)" at 1451.37,5578.94 h60
  text "-" at 2784.97,5578.94 h60
  text "-" at 3814.68,5578.94 h60
  text "2" at -5696.62,5428.94 h60
  text "1.30mm (51.18mil)" at -5046.8,5428.94 h60
  text "PTH" at -3957.12,5428.94 h60
  text "Round" at -3451.24,5428.94 h60
  text "Top Layer - Bottom Layer" at -2717.44,5428.94 h60
  text "Pad" at -1217.89,5428.94 h60
  text "(Mixed)" at -628.04,5428.94 h60
  text "0.08mm (3.00mil)" at 117.76,5428.94 h60
  text "0.08mm (3.00mil)" at 1451.37,5428.94 h60
  text "-" at 2784.97,5428.94 h60
  text "-" at 3814.68,5428.94 h60
  text "2" at -5696.62,5278.94 h60
  text "1.40mm (55.12mil)" at -5046.8,5278.94 h60
  text "NPTH" at -3957.12,5278.94 h60
  text "Round" at -3451.24,5278.94 h60
  text "Top Layer - Bottom Layer" at -2717.44,5278.94 h60
  text "Pad" at -1217.89,5278.94 h60
  text "Rounded" at -628.04,5278.94 h60
  text "0.08mm (3.00mil)" at 117.76,5278.94 h60
  text "0.08mm (3.00mil)" at 1451.37,5278.94 h60
  text "-" at 2784.97,5278.94 h60
  text "-" at 3814.68,5278.94 h60
  text "6" at -5696.62,5128.94 h60
  text "1.60mm (62.99mil)" at -5046.8,5128.94 h60
  text "PTH" at -3957.12,5128.94 h60
  text "Round" at -3451.24,5128.94 h60
  text "Top Layer - Bottom Layer" at -2717.44,5128.94 h60
  text "Pad" at -1217.89,5128.94 h60
  text "Rounded" at -628.04,5128.94 h60
  text "0.08mm (3.00mil)" at 117.76,5128.94 h60
  text "0.08mm (3.00mil)" at 1451.37,5128.94 h60
  text "-" at 2784.97,5128.94 h60
  text "-" at 3814.68,5128.94 h60
  text "2" at -5696.62,4978.94 h60
  text "3.05mm (120.08mil)" at -5046.8,4978.94 h60
  text "PTH" at -3957.12,4978.94 h60
  text "Round" at -3451.24,4978.94 h60
  text "Top Layer - Bottom Layer" at -2717.44,4978.94 h60
  text "Pad" at -1217.89,4978.94 h60
  text "Rounded" at -628.04,4978.94 h60
  text "0.13mm (5.00mil)" at 117.76,4978.94 h60
  text "0.13mm (5.00mil)" at 1451.37,4978.94 h60
  text "-" at 2784.97,4978.94 h60
  text "-" at 3814.68,4978.94 h60
  text "4" at -5696.62,4828.94 h60
  text "4.50mm (177.17mil)" at -5046.8,4828.94 h60
  text "NPTH" at -3957.12,4828.94 h60
  text "Round" at -3451.24,4828.94 h60
  text "Top Layer - Bottom Layer" at -2717.44,4828.94 h60
  text "Pad" at -1217.89,4828.94 h60
  text "Rounded" at -628.04,4828.94 h60
  text "0.13mm (5.00mil)" at 117.76,4828.94 h60
  text "0.13mm (5.00mil)" at 1451.37,4828.94 h60
  text "-" at 2784.97,4828.94 h60
  text "-" at 3814.68,4828.94 h60
  text "4" at -5696.62,4678.94 h60
  text "4.50mm (177.17mil)" at -5046.8,4678.94 h60
  text "PTH" at -3957.12,4678.94 h60
  text "Round" at -3451.24,4678.94 h60
  text "Top Layer - Bottom Layer" at -2717.44,4678.94 h60
  text "Pad" at -1217.89,4678.94 h60
  text "Rounded" at -628.04,4678.94 h60
  text "0.13mm (5.00mil)" at 117.76,4678.94 h60
  text "0.13mm (5.00mil)" at 1451.37,4678.94 h60
  text "-" at 2784.97,4678.94 h60
  text "-" at 3814.68,4678.94 h60
  text "1273 Total" at -5696.62,4528.94 h60
  text "Slot definitions :" at -6202.5,4383.97 h60
  text "Routed Path Length" at -5169.81,4383.97 h60
  text "= Calculated from tool start centre position to tool end centre position." at -4067.14,4383.97 h60
  text "Hole Length" at -5169.81,4283.99 h60
  text "= Routed Path Length + Tool Size = Slot length as defined in the PCB layout" at -4477.01,4283.99 h60

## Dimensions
-6250,-4000 to -6250,4000 on Drill Drawing
-6300,-3950 to 2700,-3950 on Drill Drawing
